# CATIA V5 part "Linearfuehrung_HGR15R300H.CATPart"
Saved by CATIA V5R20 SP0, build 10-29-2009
Part number: HGR15R300H
Source: Unknown
Description: PART--DESC
Bounding box of the stored display mesh (mm): x -7.5 to 7.5, y 25 to 275, z 0 to 15
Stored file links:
  C:\Users\Andi\Desktop\Offene Projekte\Plasmacutter\Z-Achse\Linearfuehrung_HGR15R300H.CATPart
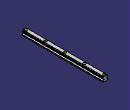
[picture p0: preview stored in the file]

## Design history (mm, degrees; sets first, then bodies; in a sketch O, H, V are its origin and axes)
Body1 "HGR15R300H_FILE" (main body)
  Solid1: solid without history
  Sketch1 on face of Solid1, origin (0, 300, 0), H (-1, 0, 0), V (0, 0, 1)
    line L1 (-7.5, 15) -> (7.5, 15)
    line L2 (7.5, 15) -> (7.5, 0)
    line L3 (7.5, 0) -> (-7.5, 0)
    line L4 (-7.5, 0) -> (-7.5, 15)
    reference intersected line E1 (6.8, 0) -> (-6.8, 0) from face of Solid1
    reference intersected line E2 (7.5, 3.2434) -> (7.5, 0.7) from face of Solid1
    reference intersected line E3 (-5.049, 15) -> (5.049, 15) from face of Solid1
    reference intersected line E4 (-7.5, 0.7) -> (-7.5, 3.2434) from face of Solid1
    horizontal: L1 H, L3 H
    vertical: L2 V, L4 V
    coincidence: E1 L3, E2 L2, E3 L1, E4 L4
  Pocket1: profile Sketch1, direction (0, -1, 0), length 25
  Sketch2 on face of Solid1, origin (0, 0, 0), H (1, 0, 0), V (0, 0, 1)
    line L1 (-7.5, 15) -> (7.5, 15)
    line L2 (7.5, 15) -> (7.5, 0)
    line L3 (7.5, 0) -> (-7.5, 0)
    line L4 (-7.5, 0) -> (-7.5, 15)
    reference intersected line E1 (-5.049, 15) -> (5.049, 15) from face of Solid1
    reference intersected line E2 (-7.5, 0.7) -> (-7.5, 3.2434) from face of Solid1
    reference intersected line E3 (6.8, 0) -> (-6.8, 0) from face of Solid1
    reference intersected line E4 (7.5, 3.2434) -> (7.5, 0.7) from face of Solid1
    horizontal: L1 H, L3 H
    vertical: L2 V, L4 V
    coincidence: E1 L1, E2 L4, E3 L3, E4 L2
  Pocket2: profile Sketch2, direction (0, 1, 0), length 25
